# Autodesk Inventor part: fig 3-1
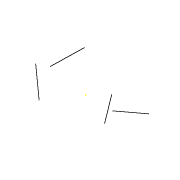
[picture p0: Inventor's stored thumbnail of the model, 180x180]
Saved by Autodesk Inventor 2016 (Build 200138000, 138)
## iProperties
Created: 2011-07
Part Number: fig 3-1
Material: Generic
Document SubType Name: Modeling
Designer: CadCim
Density: 1 g/cm^3
Appearance: Default
Author: CadCim
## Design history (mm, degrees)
sketch "Sketch1"
  geometry: L1 (-24.535, 0.895)-(-9.053, -12.994); L2 (-20.147, 3.302)-(-19.785, 19.15); L3 (5.706, 6.44)-(15.874, -7.118); L4 (12.565, -0.112)-(22.33, 7.212); 1 further point
  constraints: 8 end point, 1 perpendicular, 1 other
